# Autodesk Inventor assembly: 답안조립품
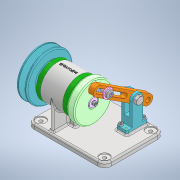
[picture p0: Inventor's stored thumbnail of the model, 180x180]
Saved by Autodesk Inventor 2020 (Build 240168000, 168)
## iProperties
Created: 2024-07
Part Number: 답안조립품
Document SubType Name: Assembly
Designer: oem
Mass: 1442.97 g
Surface Area: 1663.58 cm^2
Volume: 499.558 cm^3
Density: 2.88849 g/cm^3
Author: oem
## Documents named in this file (24)
- C:\Users\oem\Desktop\640704V1002\답안조립품.iam
- C:\Users\oem\Desktop\640704V1002\본체.ipt
- C:\Users\oem\Desktop\640704V1002\베어링 6004.ipt
- C:\Users\oem\Desktop\640704V1002\축.ipt
- C:\Users\oem\Desktop\640704V1002\커버.ipt
- C:\Users\oem\Desktop\640704V1002\육각 소켓 머리 볼트 M4x10.ipt
- C:\Users\oem\Desktop\640704V1002\오일 실 20 32 5.ipt
- C:\Users\oem\Desktop\640704V1002\평행키 5x5x12.ipt
- C:\Users\oem\Desktop\640704V1002\V-벨트풀리.ipt
- C:\Users\oem\Desktop\640704V1002\평와셔 M10.ipt
- C:\Users\oem\Desktop\640704V1002\육각 너트 M10x1.ipt
- C:\Users\oem\Desktop\640704V1002\평행키 4x4x8.ipt
- C:\Users\oem\Desktop\640704V1002\돌림판.ipt
- C:\Users\oem\Desktop\640704V1002\앤드 캡.ipt
- C:\Users\oem\Desktop\640704V1002\스프링 와셔 M4.ipt
- C:\Users\oem\Desktop\640704V1002\힌지.ipt
- C:\Users\oem\Desktop\640704V1002\핀 3 x 8.ipt
- C:\Users\oem\Desktop\640704V1002\크랭크.ipt
- C:\Users\oem\Desktop\640704V1002\힌지 축.ipt
- C:\Users\oem\Desktop\640704V1002\평와셔 M8.ipt
- C:\Users\oem\Desktop\640704V1002\육각 너트 M8.ipt
- C:\Users\oem\Desktop\640704V1002\칼라.ipt
- C:\Users\oem\Desktop\640704V1002\스페이서.ipt
- C:\Users\oem\Desktop\640704V1002\스트리퍼 볼트 8 x 30.ipt
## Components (3 placed, 2 different names)
1. V-벨트풀리:1
2. 핀 3 x 8:1
3. 핀 3 x 8:2
